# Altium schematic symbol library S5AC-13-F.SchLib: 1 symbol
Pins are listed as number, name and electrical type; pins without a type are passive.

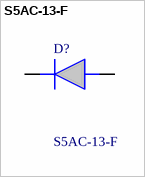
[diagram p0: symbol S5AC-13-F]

## S5AC-13-F
designator D?
Diodes Inc S5AC-13-F, SMT Diode, 50V 5A, 2-Pin DO-214AB; Manufacturer_Name: Diodes Incorporated; Geometry.Height: 2.5mm
footprint DIOM7959X250N
pins: 1 K, 2 A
